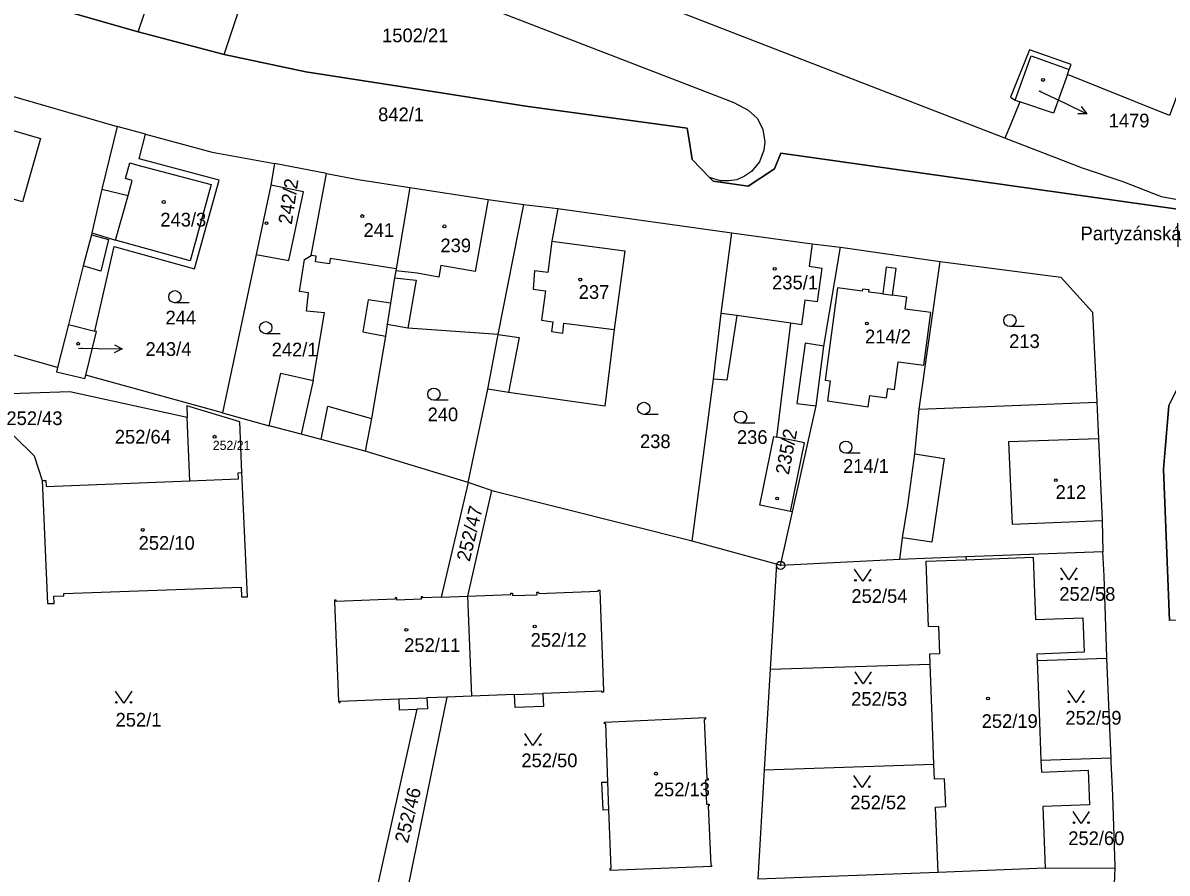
# Model space of a CAD drawing. Extents: x -737240 to -735272, y -1119606 to -1117878.
# Drawn here: x -736816.5 to -736674.7, y -1118803.8 to -1118698.3 of the extents above; entities that cross this region are included whole.
import ezdxf

# ---------------------------------------------------------------- set-up
doc = ezdxf.new("R2010")
doc.units = 0
for name, color, linetype in [('Level 1', 7, 'Continuous'), ('Level 13', 7, 'Continuous'), ('Level 15', 7, 'Continuous'), ('Level 16', 7, 'Continuous'), ('Level 18', 7, 'Continuous'), ('Level 19', 7, 'Continuous'), ('Level 25', 7, 'Continuous'), ('Level 4', 7, 'Continuous')]:
    doc.layers.add(name, color=color, linetype=linetype)

msp = doc.modelspace()

# ---------------------------------------------------------------- linework, layer by layer
at = {"layer": 'Level 1'}
for p, q in [((-736802.24, -1118699.42), (-736796.51, -1118682.14)), ((-736791.58, -1118702.24), (-736786.31, -1118686.32)), ((-736694.8, -1118712.62), (-736743.06, -1118693.88)), ((-736802.24, -1118699.42), (-736812.83, -1118696.41)), ((-736791.58, -1118702.24), (-736802.24, -1118699.42)), ((-736687.01, -1118704.7), (-736686.79, -1118704.09)), ((-736822.44, -1118706.06), (-736804.85, -1118711.17)), ((-736693.5, -1118707.91), (-736692.91, -1118708.12)), ((-736804.85, -1118711.17), (-736806.75, -1118718.96)), ((-736801.33, -1118712.12), (-736804.85, -1118711.17)), ((-736785.35, -1118715.78), (-736785.82, -1118718.45)), ((-736778.88, -1118717.01), (-736785.35, -1118715.78)), ((-736780.81, -1118727.18), (-736778.88, -1118717.01)), ((-736806.75, -1118718.96), (-736807.98, -1118724.37)), ((-736785.82, -1118718.45), (-736787.64, -1118727.04)), ((-736768.57, -1118718.72), (-736770.27, -1118728.83)), ((-736768.57, -1118718.72), (-736758.84, -1118720.22)), ((-736758.84, -1118720.22), (-736754.41, -1118720.86)), ((-736757.63, -1118736.97), (-736754.41, -1118720.86)), ((-736754.41, -1118720.86), (-736750.21, -1118721.36)), ((-736750.21, -1118721.36), (-736750.95, -1118725.39)), ((-736750.21, -1118721.36), (-736728.64, -1118724.37)), ((-736808.05, -1118724.62), (-736809.07, -1118728.48)), ((-736807.98, -1118724.37), (-736808.05, -1118724.62)), ((-736729.98, -1118734.38), (-736728.64, -1118724.37)), ((-736728.64, -1118724.37), (-736718.66, -1118725.73)), ((-736718.66, -1118725.73), (-736715.17, -1118726.14)), ((-736717.22, -1118738.43), (-736715.17, -1118726.14)), ((-736715.17, -1118726.14), (-736702.82, -1118727.92)), ((-736787.64, -1118727.04), (-736791.8, -1118746.71)), ((-736809.07, -1118728.48), (-736810.9, -1118735.74)), ((-736770.27, -1118728.83), (-736770.31, -1118729.09)), ((-736705.39, -1118746.23), (-736702.82, -1118727.92)), ((-736770.45, -1118729.97), (-736770.96, -1118733.09)), ((-736770.31, -1118729.09), (-736770.45, -1118729.97)), ((-736770.96, -1118733.09), (-736771.36, -1118735.74)), ((-736730.9, -1118742.51), (-736729.98, -1118734.38)), ((-736721.31, -1118735.59), (-736728, -1118734.64)), ((-736810.9, -1118735.74), (-736812.24, -1118741.08)), ((-736810.9, -1118735.74), (-736807.62, -1118736.57)), ((-736771.36, -1118735.74), (-736771.58, -1118737.18)), ((-736768.82, -1118736.18), (-736771.36, -1118735.74)), ((-736723.04, -1118749.71), (-736721.31, -1118735.59)), ((-736771.58, -1118737.18), (-736773.31, -1118747.42)), ((-736757.63, -1118736.97), (-736768.82, -1118736.18)), ((-736758.89, -1118743.76), (-736757.63, -1118736.97)), ((-736812.24, -1118741.08), (-736822.21, -1118738.25)), ((-736718.17, -1118745.84), (-736717.22, -1118738.43)), ((-736791.8, -1118746.71), (-736808.75, -1118742.04)), ((-736733.54, -1118762.64), (-736730.9, -1118742.51)), ((-736761.33, -1118755.36), (-736758.89, -1118743.76)), ((-736756.34, -1118744.19), (-736758.89, -1118743.76)), ((-736721.11, -1118758.99), (-736718.17, -1118745.84)), ((-736705.39, -1118746.23), (-736683.37, -1118745.4)), ((-736683.37, -1118745.4), (-736683.15, -1118749.92)), ((-736795.84, -1118755.13), (-736796.16, -1118747.3)), ((-736791.8, -1118746.71), (-736786, -1118748.3)), ((-736773.31, -1118747.42), (-736774.09, -1118751.44)), ((-736705.96, -1118751.8), (-736705.39, -1118746.23)), ((-736782.04, -1118749.36), (-736786, -1118748.3)), ((-736779.57, -1118750.03), (-736782.04, -1118749.36)), ((-736774.09, -1118751.44), (-736779.57, -1118750.03)), ((-736683.15, -1118749.92), (-736682.73, -1118760.07)), ((-736761.33, -1118755.36), (-736774.09, -1118751.44)), ((-736761.33, -1118755.36), (-736764.67, -1118769.58)), ((-736758.43, -1118756.34), (-736761.33, -1118755.36)), ((-736758.43, -1118756.34), (-736761.43, -1118769.46)), ((-736722.59, -1118765.64), (-736721.11, -1118758.99)), ((-736721.11, -1118758.99), (-736721.35, -1118758.94)), ((-736682.73, -1118760.07), (-736682.64, -1118763.96)), ((-736723.11, -1118765.5), (-736733.54, -1118762.64)), ((-736707.8, -1118764.89), (-736707.47, -1118762.22)), ((-736682.64, -1118763.96), (-736699.6, -1118764.59)), ((-736723.11, -1118765.5), (-736723.88, -1118778.53)), ((-736722.59, -1118765.64), (-736723.11, -1118765.5)), ((-736707.8, -1118764.89), (-736722.59, -1118765.64)), ((-736699.6, -1118764.59), (-736707.8, -1118764.89)), ((-736699.6, -1118764.59), (-736699.59, -1118764.93)), ((-736764.67, -1118769.58), (-736761.43, -1118769.46)), ((-736761.43, -1118769.46), (-736760.92, -1118781.86)), ((-736682.13, -1118777.19), (-736690.78, -1118777.47)), ((-736723.88, -1118778.53), (-736724.61, -1118791.01)), ((-736723.88, -1118778.53), (-736704.05, -1118777.89)), ((-736763.96, -1118781.98), (-736771.19, -1118817.07)), ((-736763.96, -1118781.98), (-736766.44, -1118782.07)), ((-736760.92, -1118781.86), (-736763.96, -1118781.98)), ((-736755.57, -1118781.65), (-736760.92, -1118781.86)), ((-736767.71, -1118783.47), (-736775.23, -1118817.33)), ((-736681.61, -1118789.54), (-736690.3, -1118789.84)), ((-736724.61, -1118791.01), (-736725.41, -1118804.57)), ((-736724.61, -1118791.01), (-736703.58, -1118790.29)), ((-736703.07, -1118803.73), (-736725.41, -1118804.57)), ((-736689.8, -1118803.22), (-736703.07, -1118803.73)), ((-736689.8, -1118803.22), (-736681.12, -1118803.16)), ((-736681.17, -1118805.15), (-736681.12, -1118803.16))]:
    msp.add_line(p, q, dxfattribs=at)
for points in [[(-736675.09, -1118625.55), (-736646.86, -1118636.43), (-736674.36, -1118709.79), (-736687.01, -1118704.7)], [(-736786.31, -1118686.32), (-736786.13, -1118685.85), (-736728.39, -1118708.19), (-736726.61, -1118709.13), (-736725.45, -1118710.18), (-736724.78, -1118711.54), (-736724.55, -1118713.09), (-736724.66, -1118714.12), (-736725.19, -1118715.56), (-736726.2, -1118716.77), (-736727.08, -1118717.35), (-736728.03, -1118717.77), (-736729, -1118717.93), (-736730.05, -1118717.92), (-736731.39, -1118717.49)], [(-736812.83, -1118696.41), (-736802.24, -1118699.42), (-736791.58, -1118702.24), (-736781.47, -1118704.4), (-736764.69, -1118707.01), (-736754.19, -1118708.64), (-736734.17, -1118711.39), (-736733.93, -1118712.88), (-736733.54, -1118715.27), (-736731.39, -1118717.49), (-736730.96, -1118717.94), (-736726.61, -1118718.57), (-736723.35, -1118716.43), (-736722.58, -1118714.49), (-736673.37, -1118721.44)], [(-736686.79, -1118704.09), (-736686.57, -1118703.46), (-736691.74, -1118701.64), (-736694.07, -1118707.55), (-736693.5, -1118707.91)], [(-736731.39, -1118717.49), (-736733.54, -1118715.27), (-736733.93, -1118712.88), (-736734.17, -1118711.39), (-736754.19, -1118708.64), (-736764.69, -1118707.01), (-736781.47, -1118704.4), (-736791.58, -1118702.24)], [(-736687.01, -1118704.7), (-736688.74, -1118709.52), (-736692.91, -1118708.12)], [(-736692.91, -1118708.12), (-736694.1, -1118710.95), (-736694.8, -1118712.62)], [(-736823.18, -1118710.1), (-736814.37, -1118712.66), (-736816.61, -1118720.52), (-736825.34, -1118718.06)], [(-736807.62, -1118736.57), (-736805.23, -1118726.07), (-736795.25, -1118728.84), (-736792.21, -1118717.81), (-736802.12, -1118715.2), (-736801.33, -1118712.12)], [(-736801.33, -1118712.12), (-736793.07, -1118714.34), (-736785.35, -1118715.78)], [(-736664.14, -1118722.6), (-736667.23, -1118721.43), (-736675.35, -1118719.88), (-736680.1, -1118718.04), (-736685.14, -1118716.33), (-736694.8, -1118712.62)], [(-736673.37, -1118721.44), (-736722.58, -1118714.49), (-736723.35, -1118716.43), (-736726.61, -1118718.57), (-736730.96, -1118717.94), (-736731.39, -1118717.49)], [(-736778.88, -1118717.01), (-736774.96, -1118717.75), (-736768.57, -1118718.72)], [(-736787.64, -1118727.04), (-736783.56, -1118727.79), (-736781.77, -1118719.27), (-736785.82, -1118718.45)], [(-736672.38, -1118772.42), (-736674.36, -1118772.47), (-736675.09, -1118753.69), (-736674.89, -1118751.22), (-736674.44, -1118745.84), (-736672.94, -1118742.81), (-736673.37, -1118721.44)], [(-736750.95, -1118725.39), (-736741.91, -1118726.59), (-736743.23, -1118736.37)], [(-736780.56, -1118742.68), (-736779.16, -1118734.3), (-736781.39, -1118734.07), (-736781.14, -1118731.8), (-736782.23, -1118731.64), (-736781.62, -1118727.68), (-736780.81, -1118727.18)], [(-736708.72, -1118732.1), (-736708.27, -1118728.8), (-736709.51, -1118728.63), (-736709.93, -1118731.94)], [(-736702.82, -1118727.92), (-736687.82, -1118729.85), (-736683.91, -1118734.21), (-736683.37, -1118745.4)], [(-736709.93, -1118731.94), (-736711.65, -1118731.71), (-736711.62, -1118731.46), (-736712.42, -1118731.36), (-736712.46, -1118731.61), (-736715.53, -1118731.2), (-736717.05, -1118742.66), (-736716.45, -1118742.74), (-736716.79, -1118745.23), (-736711.72, -1118745.94), (-736711.53, -1118744.56), (-736709.45, -1118744.84), (-736709.3, -1118743.7), (-736708.45, -1118743.81), (-736708, -1118740.36), (-736704.84, -1118740.78), (-736703.98, -1118734.25), (-736707.14, -1118733.83), (-736706.94, -1118732.33), (-736708.72, -1118732.1)], [(-736728, -1118734.64), (-736729.25, -1118742.65), (-736730.9, -1118742.51)], [(-736808.75, -1118742.04), (-736807.44, -1118736.61), (-736807.62, -1118736.57)], [(-736743.23, -1118736.37), (-736744.38, -1118745.88), (-736756.34, -1118744.19)], [(-736812.24, -1118741.08), (-736812.37, -1118741.6), (-736808.85, -1118742.46), (-736808.75, -1118742.04)], [(-736786, -1118748.3), (-736784.56, -1118741.79), (-736780.56, -1118742.68)], [(-736796.16, -1118747.3), (-736810.72, -1118744.1), (-736820.59, -1118744.43)], [(-736789.4, -1118754.11), (-736789.66, -1118747.8), (-736796.22, -1118745.82), (-736796.16, -1118747.3)], [(-736674.44, -1118745.84), (-736674.89, -1118751.22), (-736675.09, -1118753.69), (-736674.36, -1118772.47)], [(-736820.5, -1118748.74), (-736817.61, -1118749.6), (-736815.16, -1118752.06), (-736814.14, -1118755.11)], [(-736721.35, -1118758.94), (-736725.16, -1118758.17), (-736723.44, -1118749.64), (-736723.04, -1118749.71)], [(-736721.35, -1118758.94), (-736719.63, -1118750.41), (-736723.04, -1118749.71)], [(-736707.47, -1118762.22), (-736706.82, -1118758.18), (-736705.96, -1118751.8)], [(-736814.14, -1118755.11), (-736813.48, -1118770.35), (-736812.69, -1118770.36), (-736812.72, -1118769.47), (-736811.48, -1118769.43), (-736811.49, -1118769.13), (-736789.48, -1118768.34), (-736789.44, -1118769.54), (-736788.68, -1118769.52), (-736789.4, -1118754.11)], [(-736795.84, -1118755.13), (-736789.81, -1118754.88), (-736789.84, -1118754.14), (-736789.4, -1118754.11)], [(-736814.14, -1118755.11), (-736813.69, -1118755.1), (-736813.66, -1118755.85), (-736795.84, -1118755.13)], [(-736733.54, -1118762.64), (-736758.07, -1118756.46), (-736758.43, -1118756.34)], [(-736682.13, -1118777.19), (-736682.14, -1118777.03), (-736682.48, -1118766.94), (-736682.64, -1118763.96)], [(-736704.05, -1118777.89), (-736704.1, -1118776.63), (-736702.85, -1118776.58), (-736702.98, -1118773.21), (-736704.23, -1118773.25), (-736704.55, -1118765.12), (-736699.59, -1118764.93)], [(-736699.59, -1118764.93), (-736691.27, -1118764.61), (-736690.97, -1118772.37), (-736685.13, -1118772.15), (-736684.96, -1118776.42), (-736690.81, -1118776.65), (-736690.78, -1118777.47)], [(-736761.43, -1118769.46), (-736756.03, -1118769.25), (-736756.04, -1118769.1), (-736755.84, -1118769.09), (-736755.83, -1118769.39), (-736752.79, -1118769.27), (-736752.8, -1118768.97), (-736752.6, -1118768.96), (-736752.59, -1118769.11), (-736745.22, -1118768.82), (-736745.22, -1118768.72), (-736745.02, -1118768.71), (-736745.02, -1118768.81), (-736744.56, -1118781.22), (-736744.56, -1118781.36), (-736744.76, -1118781.36), (-736744.76, -1118781.24), (-736752.06, -1118781.52)], [(-736764.67, -1118769.58), (-736766.95, -1118769.67), (-736766.95, -1118769.52), (-736767.15, -1118769.53), (-736767.14, -1118769.83), (-736770.18, -1118769.95), (-736770.19, -1118769.65), (-736770.39, -1118769.65), (-736770.39, -1118769.81), (-736777.71, -1118770.1), (-736777.72, -1118769.95), (-736777.92, -1118769.95), (-736777.91, -1118770.1), (-736777.4, -1118782.5), (-736777.39, -1118782.65), (-736777.19, -1118782.64), (-736777.2, -1118782.49), (-736769.93, -1118782.21)], [(-736681.61, -1118789.54), (-736681.74, -1118786.75), (-736682.13, -1118777.19)], [(-736703.58, -1118790.29), (-736703.81, -1118784.41), (-736704.05, -1118777.89)], [(-736690.78, -1118777.47), (-736690.53, -1118783.91), (-736690.3, -1118789.84)], [(-736752.06, -1118781.52), (-736751.99, -1118783.15), (-736755.51, -1118783.29), (-736755.57, -1118781.65)], [(-736769.93, -1118782.21), (-736769.87, -1118783.54), (-736767.71, -1118783.47)], [(-736766.44, -1118782.07), (-736766.39, -1118783.42), (-736767.71, -1118783.47)], [(-736744, -1118792.52), (-736744.28, -1118785.27), (-736744.43, -1118785.28), (-736744.44, -1118785.08), (-736731.91, -1118784.53), (-736731.9, -1118784.72), (-736732.05, -1118784.74), (-736731.73, -1118792.09), (-736731.58, -1118792.08), (-736731.57, -1118792.28), (-736731.92, -1118792.29), (-736731.79, -1118795.28), (-736731.44, -1118795.26), (-736731.43, -1118795.46), (-736731.58, -1118795.47), (-736731.26, -1118802.82), (-736731.16, -1118802.82), (-736731.15, -1118803.02), (-736743.73, -1118803.49), (-736743.74, -1118803.24), (-736743.59, -1118803.24), (-736743.87, -1118795.99)], [(-736690.3, -1118789.84), (-736690.25, -1118791.28), (-736684.44, -1118791.06), (-736684.28, -1118795.34), (-736690.08, -1118795.56), (-736689.8, -1118803.22)], [(-736681.12, -1118803.16), (-736681.12, -1118803), (-736681.38, -1118794.18), (-736681.59, -1118789.96), (-736681.61, -1118789.54)], [(-736703.07, -1118803.73), (-736703.38, -1118795.62), (-736702.12, -1118795.57), (-736702.26, -1118792.13), (-736703.51, -1118792.17), (-736703.58, -1118790.29)], [(-736743.87, -1118795.99), (-736744.61, -1118796.02), (-736744.74, -1118792.54), (-736744, -1118792.52)]]:
    msp.add_lwpolyline(points, dxfattribs=at)
at = {"layer": 'Level 13'}
for points in [[(-736827.96, -1118694.72), (-736827.03, -1118692.81), (-736826.75, -1118692.23), (-736823.37, -1118693.24), (-736812.83, -1118696.41), (-736802.24, -1118699.42), (-736791.58, -1118702.24), (-736781.47, -1118704.4), (-736764.69, -1118707.01), (-736754.19, -1118708.64), (-736734.17, -1118711.39), (-736733.93, -1118712.88), (-736733.54, -1118715.27), (-736731.39, -1118717.49), (-736730.96, -1118717.94), (-736726.61, -1118718.57), (-736723.35, -1118716.43), (-736722.58, -1118714.49), (-736673.37, -1118721.44)], [(-736812.83, -1118696.41), (-736802.24, -1118699.42), (-736791.58, -1118702.24), (-736781.47, -1118704.4), (-736764.69, -1118707.01), (-736754.19, -1118708.64), (-736734.17, -1118711.39), (-736733.93, -1118712.88), (-736733.54, -1118715.27), (-736731.39, -1118717.49), (-736730.96, -1118717.94), (-736726.61, -1118718.57), (-736723.35, -1118716.43), (-736722.58, -1118714.49), (-736673.37, -1118721.44)], [(-736674.44, -1118745.84), (-736674.89, -1118751.22), (-736675.09, -1118753.69), (-736674.36, -1118772.47)], [(-736674.44, -1118745.84), (-736674.89, -1118751.22), (-736675.09, -1118753.69), (-736674.36, -1118772.47)]]:
    msp.add_lwpolyline(points, dxfattribs=at)
at = {"layer": 'Level 16'}
for points in [[(-736690.55, -1118706.75), (-736687.32, -1118708.29), (-736684.612, -1118709.58)], [(-736685.299, -1118708.699), (-736684.612, -1118709.58), (-736685.73, -1118709.602)], [(-736809.67, -1118738.66), (-736807.22, -1118738.71), (-736804.221, -1118738.776)], [(-736805.209, -1118738.254), (-736804.221, -1118738.776), (-736805.231, -1118739.254)]]:
    msp.add_lwpolyline(points, dxfattribs=at)
at = {"layer": 'Level 25'}
for p, q in [((-736795.918, -1118733.05), (-736797.7, -1118733.05)), ((-736692.378, -1118736.01), (-736694.16, -1118736.01)), ((-736784.648, -1118736.89), (-736786.43, -1118736.89)), ((-736763.798, -1118745.15), (-736765.58, -1118745.15)), ((-736737.778, -1118746.9), (-736739.56, -1118746.9)), ((-736725.768, -1118748), (-736727.55, -1118748)), ((-736712.718, -1118751.72), (-736714.5, -1118751.72))]:
    msp.add_line(p, q, dxfattribs=at)
for points in [[(-736711.41, -1118766.09), (-736712.41, -1118767.59), (-736713.41, -1118766.09)], [(-736685.84, -1118765.92), (-736686.84, -1118767.42), (-736687.84, -1118765.92)], [(-736711.36, -1118778.85), (-736712.36, -1118780.35), (-736713.36, -1118778.85)], [(-736803.05, -1118781.23), (-736804.05, -1118782.73), (-736805.05, -1118781.23)], [(-736684.95, -1118781.17), (-736685.95, -1118782.67), (-736686.95, -1118781.17)], [(-736752.3, -1118786.48), (-736753.3, -1118787.98), (-736754.3, -1118786.48)], [(-736711.49, -1118791.7), (-736712.49, -1118793.2), (-736713.49, -1118791.7)], [(-736684.31, -1118796.17), (-736685.31, -1118797.67), (-736686.31, -1118796.17)]]:
    msp.add_lwpolyline(points, dxfattribs=at)
for centre in [(-736687.74, -1118767.32), (-736685.94, -1118767.32), (-736713.31, -1118767.49), (-736711.51, -1118767.49), (-736713.26, -1118780.25), (-736711.46, -1118780.25), (-736804.95, -1118782.63), (-736803.15, -1118782.63), (-736686.85, -1118782.57), (-736685.05, -1118782.57), (-736754.2, -1118787.88), (-736752.4, -1118787.88), (-736713.39, -1118793.1), (-736711.59, -1118793.1), (-736686.21, -1118797.57), (-736684.41, -1118797.57)]:
    msp.add_circle(centre, 0.1, dxfattribs=at)
for centre, major_axis, ratio in [((-736690.04, -1118705.39), (0.18, 0), 0.9848078), ((-736799.09, -1118720.54), (0.18, 0), 0.9848078), ((-736786.34, -1118723.16), (0.18, 0), 0.9848078), ((-736774.46, -1118722.28), (0.18, 0), 0.9848078), ((-736764.28, -1118723.56), (0.18, 0), 0.9848078), ((-736723.32, -1118728.84), (0.18, 0), 0.9848078), ((-736747.43, -1118730.17), (0.18, 0), 0.9848078), ((-736797.7, -1118732.294), (0.764, 0), 0.9894236), ((-736694.16, -1118735.254), (0.764, 0), 0.9894236), ((-736786.43, -1118736.134), (0.764, 0), 0.9894236), ((-736711.9, -1118735.62), (0.18, 0), 0.9848078), ((-736809.69, -1118738.13), (0.18, 0), 0.9848078), ((-736765.58, -1118744.394), (0.764, 0), 0.9894236), ((-736739.56, -1118746.144), (0.764, 0), 0.9894236), ((-736727.55, -1118747.244), (0.764, 0), 0.9894236), ((-736792.78, -1118749.67), (0.18, 0), 0.9848078), ((-736714.5, -1118750.964), (0.764, 0), 0.9894236), ((-736688.46, -1118755.06), (0.18, 0), 0.9848078), ((-736723.01, -1118757.33), (0.18, 0), 0.9848078), ((-736801.69, -1118761.24), (0.18, 0), 0.9848078), ((-736722.59, -1118765.64), (0.516, 0), 0.9848078), ((-736722.59, -1118765.64), (0.0375, 0), 0.9848078), ((-736769, -1118773.63), (0.18, 0), 0.9848078), ((-736753.08, -1118773.22), (0.18, 0), 0.9848078), ((-736696.88, -1118782.15), (0.18, 0), 0.9848078), ((-736738.04, -1118791.49), (0.18, 0), 0.9848078)]:
    msp.add_ellipse(centre, major_axis=major_axis, ratio=ratio, dxfattribs=at)
at = {"layer": 'Level 4'}
for p, q in [((-736806.75, -1118718.96), (-736803.51, -1118719.72)), ((-736805.05, -1118725.29), (-736803.51, -1118719.72)), ((-736807.98, -1118724.37), (-736805.05, -1118725.29)), ((-736709.93, -1118731.94), (-736708.72, -1118732.1)), ((-736728, -1118734.64), (-736729.98, -1118734.38)), ((-736780.56, -1118742.68), (-736782.04, -1118749.36)), ((-736755.57, -1118781.65), (-736752.06, -1118781.52)), ((-736769.93, -1118782.21), (-736766.44, -1118782.07)), ((-736743.87, -1118795.99), (-736744, -1118792.52))]:
    msp.add_line(p, q, dxfattribs=at)
for points in [[(-736693.5, -1118707.91), (-736691.52, -1118702.39), (-736686.79, -1118704.09)], [(-736803.51, -1118719.72), (-736802.99, -1118717.87), (-736803.84, -1118717.64), (-736803.3, -1118715.69), (-736802.45, -1118715.93), (-736793.19, -1118718.38), (-736795.81, -1118727.85), (-736805.05, -1118725.29)], [(-736758.84, -1118720.22), (-736760.46, -1118729.18), (-736764.71, -1118728.41), (-736764.98, -1118729.87), (-736767.64, -1118729.37), (-736770.31, -1118729.09)], [(-736808.05, -1118724.62), (-736805.92, -1118725.21), (-736806.88, -1118729.11), (-736809.07, -1118728.48)], [(-736750.95, -1118725.39), (-736751.46, -1118729.29), (-736753.1, -1118729.07), (-736753.29, -1118731.35), (-736751.76, -1118731.55), (-736752.25, -1118735.21), (-736750.83, -1118735.39), (-736750.99, -1118736.63), (-736749.61, -1118736.83), (-736749.45, -1118735.57), (-736743.23, -1118736.37)], [(-736718.66, -1118725.73), (-736719.04, -1118728.52), (-736717.48, -1118728.73), (-736718.05, -1118732.94), (-736719.59, -1118732.73), (-736720, -1118735.77), (-736721.31, -1118735.59)], [(-736770.27, -1118728.83), (-736778.43, -1118727.55), (-736778.54, -1118728.23), (-736780.28, -1118727.96), (-736780.17, -1118727.28), (-736780.81, -1118727.18)], [(-736770.45, -1118729.97), (-736767.79, -1118730.25), (-736768.82, -1118736.18)], [(-736770.96, -1118733.09), (-736773.75, -1118732.66), (-736774.38, -1118736.65), (-736771.58, -1118737.18)], [(-736757.63, -1118736.97), (-736755.02, -1118737.35), (-736756.34, -1118744.19)], [(-736717.22, -1118738.43), (-736719.54, -1118738.07), (-736720.56, -1118745.55), (-736718.17, -1118745.84)], [(-736779.57, -1118750.03), (-736778.73, -1118745.89), (-736773.31, -1118747.42)], [(-736683.15, -1118749.92), (-736694.31, -1118750.32), (-736693.87, -1118760.5), (-736682.73, -1118760.07)], [(-736705.96, -1118751.8), (-736702.3, -1118752.35), (-736703.84, -1118762.75), (-736707.47, -1118762.22)]]:
    msp.add_lwpolyline(points, dxfattribs=at)

# ---------------------------------------------------------------- texts
at = {"layer": 'Level 15'}
msp.add_text('Partyzánská', height=1.7, rotation=0.00342, dxfattribs=at).set_placement((-736685.39, -1118725.29))
at = {"layer": 'Level 16'}
for s, p in [('1479', (-736681.91, -1118711.28)), ('243/4', (-736801.345, -1118739.64)), ('252/43', (-736818.59, -1118748.22))]:
    msp.add_text(s, height=1.7, dxfattribs=at).set_placement(p)
at = {"layer": 'Level 18'}
for s, p in [('1502/21', (-736772.005, -1118700.71)), ('842/1', (-736772.495, -1118710.52)), ('244', (-736798.865, -1118735.73)), ('213', (-736694.245, -1118738.66)), ('242/1', (-736785.7, -1118739.7)), ('240', (-736766.365, -1118747.75)), ('252/64', (-736805.15, -1118750.52)), ('236', (-736728.005, -1118750.56)), ('238', (-736740.025, -1118751.08)), ('214/1', (-736714.845, -1118754.15)), ('252/54', (-736713.81, -1118770.29)), ('252/58', (-736688.03, -1118770.03)), ('252/53', (-736713.84, -1118783.05)), ('252/1', (-736805.055, -1118785.64)), ('252/59', (-736687.27, -1118785.4)), ('252/50', (-736754.73, -1118790.68)), ('252/52', (-736713.95, -1118795.9)), ('252/60', (-736686.92, -1118800.34))]:
    msp.add_text(s, height=1.7, dxfattribs=at).set_placement(p)
for s, rotation, p in [('252/47', 76.3254, (-736761.147, -1118765.252)), ('252/46', 76.11417, (-736768.818, -1118800.195))]:
    msp.add_text(s, height=1.7, rotation=rotation, dxfattribs=at).set_placement(p)
at = {"layer": 'Level 19'}
for s, height, p in [('1479', 0.1, (-736690.425, -1118706.75)), ('243/3', 1.7, (-736799.5, -1118723.58)), ('241', 1.7, (-736774.31, -1118724.87)), ('239', 1.7, (-736764.77, -1118726.78)), ('235/1', 1.7, (-736723.64, -1118731.38)), ('237', 1.7, (-736747.62, -1118732.56)), ('214/2', 1.7, (-736712.12, -1118738.08)), ('243/4', 0.1, (-736809.52, -1118738.66)), ('252/21', 1.14, (-736792.995, -1118751.31)), ('212', 1.7, (-736688.49, -1118757.38)), ('252/10', 1.7, (-736802.195, -1118763.7)), ('252/12', 1.7, (-736753.585, -1118775.74)), ('252/11', 1.7, (-736769.265, -1118776.38)), ('252/19', 1.7, (-736697.655, -1118785.81)), ('252/13', 1.7, (-736738.305, -1118794.29))]:
    msp.add_text(s, height=height, dxfattribs=at).set_placement(p)
for s, rotation, p in [('242/2', 81.47799, (-736783.21, -1118723.4)), ('235/2', 79.26255, (-736721.575, -1118754.465))]:
    msp.add_text(s, height=1.7, rotation=rotation, dxfattribs=at).set_placement(p)

doc.saveas('drawing.dxf')
